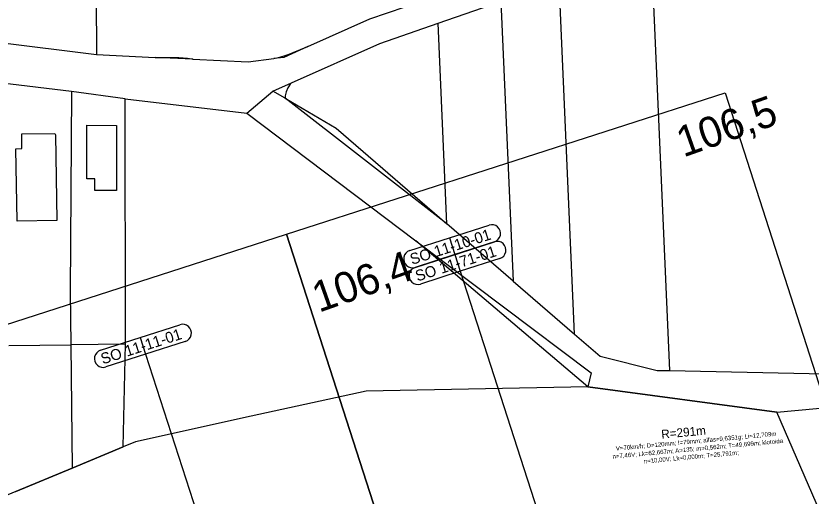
# Model space of a CAD drawing. Extents: x -758836 to -757729, y -1175316 to -1174366.
# Drawn here: x -758279.4 to -758098.2, y -1174750.5 to -1174641.1 of the extents above; entities that cross this region are included whole.
import ezdxf

# ---------------------------------------------------------------- set-up
doc = ezdxf.new("R2010")
doc.units = 0
for name, color, linetype in [('_NOR-pomocná', 7, 'Continuous'), ('_NOR-popis', 7, 'Continuous'), ('G_Obvod stavby', 7, 'Continuous'), ('Hranice parcel', 7, 'Continuous'), ('Vrstva 7', 7, 'Continuous')]:
    doc.layers.add(name, color=color, linetype=linetype)

msp = doc.modelspace()

# ---------------------------------------------------------------- linework, layer by layer
at = {"layer": '_NOR-pomocná'}
for p, q in [((-758180.62, -1174691.68), (-758179.39, -1174695.49)), ((-758179.39, -1174695.49), (-758178.16, -1174699.3)), ((-758251.08, -1174714.38), (-758249.86, -1174718.19))]:
    msp.add_line(p, q, dxfattribs=at)
for points in [[(-758217.71, -1174690.84), (-758117.77, -1174658.65), (-758072.24, -1174800), (-758172.18, -1174832.19)], [(-758317.65, -1174723.03), (-758217.71, -1174690.84), (-758172.18, -1174832.19), (-758272.12, -1174864.38)]]:
    msp.add_lwpolyline(points, close=True, dxfattribs=at)
at = {"layer": '_NOR-popis'}
for points in [[(-758189.66, -1174694.59), (-758171.57, -1174688.77)], [(-758188.43, -1174698.4), (-758170.35, -1174692.58)], [(-758170.35, -1174692.58), (-758179.39, -1174695.49)], [(-758179.39, -1174695.49), (-758188.43, -1174698.4)], [(-758169.12, -1174696.38), (-758178.16, -1174699.3), (-758157.53, -1174763.36)], [(-758178.16, -1174699.3), (-758187.21, -1174702.21)], [(-758260.13, -1174717.29), (-758242.04, -1174711.47)], [(-758240.81, -1174715.27), (-758249.86, -1174718.19), (-758235.71, -1174762.12)], [(-758249.86, -1174718.19), (-758258.9, -1174721.1)]]:
    msp.add_lwpolyline(points, dxfattribs=at)
for centre, start, end in [((-758170.96, -1174690.67), 287.8533, 107.854), ((-758169.73, -1174694.48), 287.8533, 107.854), ((-758189.04, -1174696.5), 107.854, 287.8547), ((-758187.82, -1174700.31), 107.854, 287.8547), ((-758241.43, -1174713.37), 287.8533, 107.854), ((-758259.51, -1174719.2), 107.854, 287.8547)]:
    msp.add_arc(centre, 2, start, end, dxfattribs=at)
at = {"layer": 'G_Obvod stavby'}
msp.add_lwpolyline([(-758392.72, -1174840.76), (-758391.23, -1174838.56), (-758368.37, -1174821.64), (-758340.31, -1174807.33), (-758320.27, -1174796.89), (-758301, -1174790.21), (-758267.96, -1174782.93), (-758224.96, -1174775.27), (-758184.87, -1174772.83), (-758142.71, -1174770.26), (-758089.84, -1174768.68), (-758106.02, -1174731.44), (-758149.09, -1174725.67), (-758199.62, -1174726.6), (-758225.76, -1174732.36), (-758252.17, -1174738.18), (-758254.97, -1174739.34), (-758266.58, -1174744.16), (-758279.45, -1174749.49), (-758302.42, -1174759.02), (-758331.68, -1174770.24), (-758367.17, -1174799.81), (-758405.64, -1174832.2)], dxfattribs=at)
at = {"layer": 'Hranice parcel'}
for p, q in [((-758261.42, -1174607.5), (-758261.03, -1174649.91)), ((-758134.62, -1174626.06), (-758130.45, -1174721.94)), ((-758152.07, -1174713.65), (-758155.57, -1174633.26)), ((-758183.21, -1174642.76), (-758168.89, -1174637.84)), ((-758168.89, -1174637.84), (-758166.12, -1174701.53)), ((-758181.22, -1174688.49), (-758183.21, -1174642.76)), ((-758285.9, -1174646.82), (-758261.03, -1174649.91)), ((-758261.03, -1174649.91), (-758247.67, -1174650.53)), ((-758239.06, -1174650.93), (-758247.67, -1174650.53)), ((-758266.75, -1174658.35), (-758282.56, -1174656.41)), ((-758220.83, -1174658.22), (-758216.61, -1174656.33)), ((-758254.5, -1174659.99), (-758266.75, -1174658.35)), ((-758226.78, -1174663.24), (-758220.83, -1174658.22)), ((-758218.05, -1174659.86), (-758220.83, -1174658.22)), ((-758254.45, -1174715.89), (-758254.5, -1174659.99)), ((-758254.5, -1174659.99), (-758226.78, -1174663.24)), ((-758181.22, -1174688.49), (-758218.05, -1174659.86)), ((-758226.78, -1174663.24), (-758188.26, -1174692.33)), ((-758166.12, -1174701.53), (-758181.22, -1174688.49)), ((-758149.09, -1174725.67), (-758188.26, -1174692.33)), ((-758166.12, -1174701.53), (-758152.07, -1174713.65)), ((-758254.45, -1174715.89), (-758266.93, -1174716.05)), ((-758254.97, -1174739.34), (-758254.45, -1174715.89)), ((-758281.06, -1174716.22), (-758266.93, -1174716.05)), ((-758266.93, -1174716.05), (-758266.58, -1174744.16)), ((-758266.58, -1174744.16), (-758254.97, -1174739.34)), ((-758279.45, -1174749.49), (-758266.58, -1174744.16))]:
    msp.add_line(p, q, dxfattribs=at)
for points in [[(-758212.86, -1174648.07), (-758198.75, -1174641.76), (-758182.68, -1174636.24)], [(-758216.61, -1174656.33), (-758196.5, -1174647.34), (-758183.21, -1174642.76)], [(-758220.63, -1174650.81), (-758219.98, -1174650.66), (-758219, -1174650.41), (-758218.05, -1174650.11), (-758217.1, -1174649.77), (-758216.19, -1174649.41), (-758212.86, -1174648.07)], [(-758212.86, -1174648.07), (-758218.37, -1174650.54), (-758220.63, -1174650.81)], [(-758247.67, -1174650.53), (-758245.32, -1174650.56), (-758243.31, -1174650.57), (-758242.31, -1174650.6), (-758241.31, -1174650.66), (-758240.32, -1174650.75), (-758239.33, -1174650.89), (-758239.06, -1174650.93)], [(-758239.06, -1174650.93), (-758226.51, -1174651.52), (-758220.63, -1174650.81)], [(-758216.61, -1174656.33), (-758216.89, -1174656.64), (-758217.45, -1174657.45), (-758217.83, -1174658.36), (-758218.03, -1174659.32), (-758218.05, -1174659.86)], [(-758266.75, -1174658.35), (-758267.08, -1174704.07), (-758266.93, -1174716.05)], [(-758218.05, -1174659.86), (-758206.46, -1174666.7), (-758181.22, -1174688.49)], [(-758261.43, -1174678.26), (-758263.22, -1174678.26), (-758263.23, -1174665.98), (-758256.5, -1174666.04), (-758256.48, -1174678.31), (-758256.48, -1174680.88), (-758261.39, -1174680.88), (-758261.43, -1174678.26)], [(-758278.1, -1174667.99), (-758270.51, -1174667.9), (-758270.38, -1174668.23), (-758270.07, -1174687.69), (-758279.14, -1174687.84), (-758279.41, -1174671.35), (-758278.04, -1174671.32), (-758278.1, -1174667.99)], [(-758188.26, -1174692.33), (-758148.33, -1174722.48), (-758149.09, -1174725.67)], [(-758152.07, -1174713.65), (-758146.25, -1174718.68), (-758133.29, -1174721.88), (-758130.45, -1174721.94)], [(-758149.09, -1174725.67), (-758106.02, -1174731.44), (-758087.1, -1174729.64), (-758040.84, -1174714.91), (-758029.32, -1174712.86), (-758023.54, -1174719.17), (-758013.3, -1174714.07)], [(-758130.45, -1174721.94), (-758095.02, -1174722.68), (-758089.97, -1174720.79)], [(-758149.09, -1174725.67), (-758199.62, -1174726.6), (-758225.76, -1174732.36), (-758252.17, -1174738.18), (-758254.97, -1174739.34)]]:
    msp.add_lwpolyline(points, dxfattribs=at)

# ---------------------------------------------------------------- texts
at = {"layer": '_NOR-popis'}
for s, height, rotation, p in [('SO 11-10-01', 2.5, 17.854, (-758189.13, -1174697.84)), ('SO 11-71-01', 2.5, 17.854, (-758187.91, -1174701.65)), ('SO 11-11-01', 2.5, 17.854, (-758259.6, -1174720.54)), ('R=291m', 2, 5.3025, (-758132.23, -1174737.47)), ('n=7,46V; Lk=62,667m; A=135; m=0,562m; T=49,699m; klotoida', 1, 5.3025, (-758143.4, -1174742.02)), ('V=70km/h; D=120mm; I=79mm; alfas=9,6351g; Li=12,709m', 1, 5.3025, (-758142.63, -1174740.19)), ('n=10,00V; Lk=0,000m; T=25,791m;', 1, 5.3025, (-758136.28, -1174743.11))]:
    msp.add_text(s, height=height, rotation=rotation, dxfattribs=at).set_placement(p)
at = {"layer": 'Vrstva 7'}
for s, p in [('106,5', (-758127.3, -1174673.38)), ('106,4', (-758210.35, -1174708.76))]:
    msp.add_text(s, height=6.972, rotation=19.4575, dxfattribs=at).set_placement(p)

doc.saveas('drawing.dxf')
